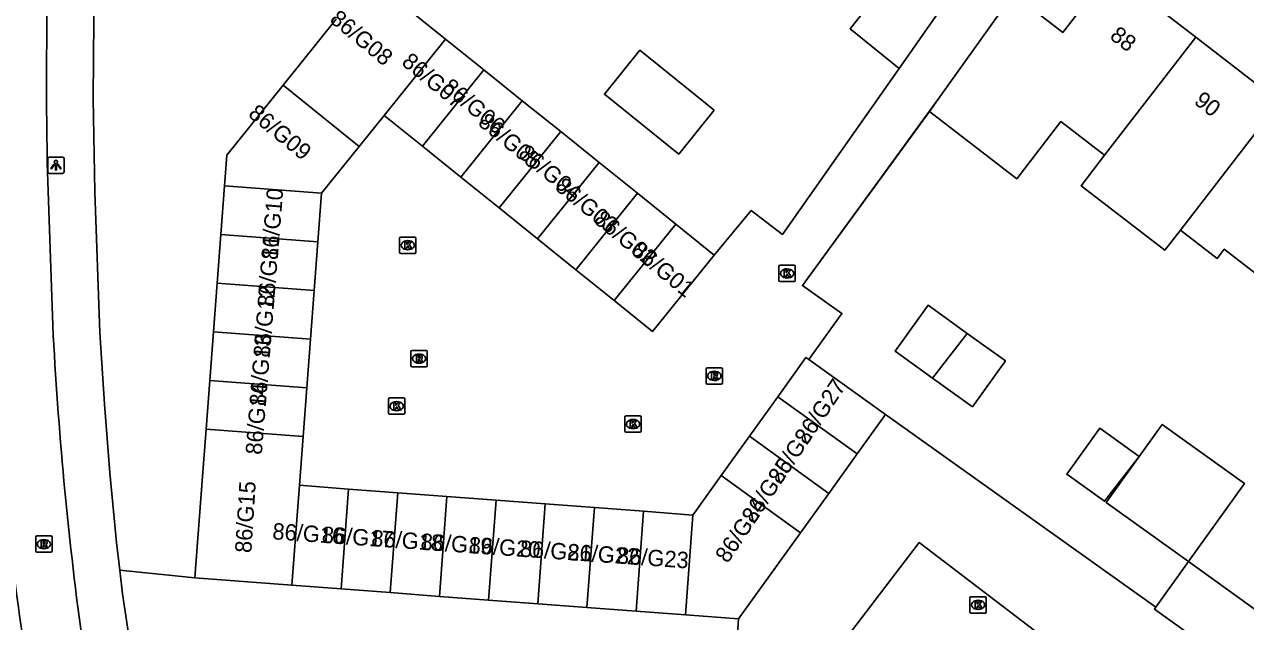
# Model space of a CAD drawing. Extents: x 160158 to 160921, y 381517 to 382041.
# Drawn here: x 160533.3 to 160607.8, y 381626.4 to 381662.9 of the extents above; entities that cross this region are included whole.
import ezdxf

# ---------------------------------------------------------------- set-up
doc = ezdxf.new("R2010")
doc.units = 0
for name, color, linetype in [('IMGEO_Fietspad_gesloten', 7, 'Continuous'), ('IMGEO_Groenvoorziening', 7, 'Continuous'), ('IMGEO_Kolk', 7, 'Continuous'), ('IMGEO_Lichtpunt', 7, 'Continuous'), ('IMGEO_Muur', 7, 'Continuous'), ('IMGEO_Pand', 7, 'Continuous'), ('IMGEO_Pand_nummerreeks', 7, 'Continuous'), ('IMGEO_Parkeervlak_open', 7, 'Continuous'), ('IMGEO_Rijbaan_lokaal_open', 7, 'Continuous'), ('IMGEO_Rioolput', 7, 'Continuous'), ('IMGEO_Voetpad_open', 7, 'Continuous')]:
    doc.layers.add(name, color=color, linetype=linetype)

msp = doc.modelspace()

# ---------------------------------------------------------------- linework, layer by layer
at = {"layer": 'IMGEO_Fietspad_gesloten'}
msp.add_lwpolyline([(160535.005, 381644.503), (160534.672, 381654.468)], dxfattribs=at)
for centre, radius, start, end in [((160815.535, 381659.561), 280.909, 175.73703, 181.03881), ((160691.29, 381649.45), 159.925, 181.41276, 189.10853), ((160764.179, 381656.242), 229.475, 182.93225, 187.69127)]:
    msp.add_arc(centre, radius, start, end, dxfattribs=at)
at = {"layer": 'IMGEO_Groenvoorziening'}
msp.add_lwpolyline([(160543.681, 381629.096), (160539.1, 381629.573)], dxfattribs=at)
at = {"layer": 'IMGEO_Kolk'}
for p, q in [((160556.181, 381648.991), (160556.181, 381649.843)), ((160556.256, 381649.917), (160557.108, 381649.917)), ((160556.669, 381649.697), (160556.694, 381649.697)), ((160557.182, 381649.843), (160557.182, 381648.991)), ((160557.108, 381648.917), (160556.256, 381648.917)), ((160556.692, 381649.137), (160556.667, 381649.137)), ((160579.348, 381647.268), (160579.348, 381648.12)), ((160579.423, 381648.194), (160580.275, 381648.194)), ((160580.349, 381648.12), (160580.349, 381647.268)), ((160579.859, 381647.414), (160579.834, 381647.414)), ((160579.836, 381647.974), (160579.861, 381647.974)), ((160580.275, 381647.194), (160579.423, 381647.194)), ((160555.506, 381639.162), (160555.506, 381640.014)), ((160555.581, 381640.088), (160556.433, 381640.088)), ((160555.994, 381639.868), (160556.019, 381639.868)), ((160556.507, 381640.014), (160556.507, 381639.162)), ((160556.017, 381639.308), (160555.992, 381639.308)), ((160556.433, 381639.088), (160555.581, 381639.088)), ((160569.938, 381638.065), (160569.938, 381638.917)), ((160570.013, 381638.991), (160570.865, 381638.991)), ((160570.426, 381638.771), (160570.451, 381638.771)), ((160570.939, 381638.917), (160570.939, 381638.065)), ((160570.865, 381637.991), (160570.013, 381637.991)), ((160570.449, 381638.211), (160570.424, 381638.211)), ((160591.084, 381627.948), (160591.936, 381627.948)), ((160591.009, 381627.022), (160591.009, 381627.874)), ((160591.497, 381627.728), (160591.522, 381627.728)), ((160592.01, 381627.874), (160592.01, 381627.022)), ((160591.936, 381626.948), (160591.084, 381626.948)), ((160591.52, 381627.168), (160591.495, 381627.168))]:
    msp.add_line(p, q, dxfattribs=at)
for points in [[(160556.181, 381648.991), (160556.181, 381649.843)], [(160556.256, 381649.917), (160557.108, 381649.917)], [(160556.502, 381649.617), (160556.625, 381649.617), (160556.625, 381649.466), (160556.755, 381649.617), (160556.919, 381649.617), (160556.773, 381649.466), (160556.926, 381649.217), (160556.774, 381649.217), (160556.689, 381649.381), (160556.625, 381649.314), (160556.625, 381649.217), (160556.502, 381649.217), (160556.502, 381649.617)], [(160557.182, 381649.843), (160557.182, 381648.991)], [(160557.108, 381648.917), (160556.256, 381648.917)], [(160579.348, 381647.268), (160579.348, 381648.12)], [(160579.423, 381648.194), (160580.275, 381648.194)], [(160580.349, 381648.12), (160580.349, 381647.268)], [(160579.669, 381647.894), (160579.792, 381647.894), (160579.792, 381647.743), (160579.922, 381647.894), (160580.086, 381647.894), (160579.94, 381647.743), (160580.093, 381647.494), (160579.941, 381647.494), (160579.856, 381647.658), (160579.792, 381647.591), (160579.792, 381647.494), (160579.669, 381647.494), (160579.669, 381647.894)], [(160580.275, 381647.194), (160579.423, 381647.194)], [(160555.506, 381639.162), (160555.506, 381640.014)], [(160555.581, 381640.088), (160556.433, 381640.088)], [(160556.507, 381640.014), (160556.507, 381639.162)], [(160555.827, 381639.788), (160555.95, 381639.788), (160555.95, 381639.637), (160556.08, 381639.788), (160556.244, 381639.788), (160556.098, 381639.637), (160556.251, 381639.388), (160556.099, 381639.388), (160556.014, 381639.552), (160555.95, 381639.485), (160555.95, 381639.388), (160555.827, 381639.388), (160555.827, 381639.788)], [(160556.433, 381639.088), (160555.581, 381639.088)], [(160569.938, 381638.065), (160569.938, 381638.917)], [(160570.013, 381638.991), (160570.865, 381638.991)], [(160570.259, 381638.691), (160570.382, 381638.691), (160570.382, 381638.54), (160570.512, 381638.691), (160570.676, 381638.691), (160570.53, 381638.54), (160570.683, 381638.291), (160570.531, 381638.291), (160570.446, 381638.455), (160570.382, 381638.388), (160570.382, 381638.291), (160570.259, 381638.291), (160570.259, 381638.691)], [(160570.939, 381638.917), (160570.939, 381638.065)], [(160570.865, 381637.991), (160570.013, 381637.991)], [(160591.084, 381627.948), (160591.936, 381627.948)], [(160591.009, 381627.022), (160591.009, 381627.874)], [(160591.33, 381627.648), (160591.453, 381627.648), (160591.453, 381627.497), (160591.583, 381627.648), (160591.747, 381627.648), (160591.601, 381627.497), (160591.754, 381627.248), (160591.602, 381627.248), (160591.517, 381627.412), (160591.453, 381627.345), (160591.453, 381627.248), (160591.33, 381627.248), (160591.33, 381627.648)], [(160592.01, 381627.874), (160592.01, 381627.022)], [(160591.936, 381626.948), (160591.084, 381626.948)]]:
    msp.add_lwpolyline(points, dxfattribs=at)
for centre, start, end in [((160556.258, 381649.841), 91.55205, 178.44795), ((160556.258, 381649.841), 91.55205, 178.44795), ((160557.106, 381649.841), 1.55205, 88.44795), ((160557.106, 381649.841), 1.55205, 88.44795), ((160556.258, 381648.993), 181.55205, 268.44795), ((160556.258, 381648.993), 181.55205, 268.44795), ((160557.106, 381648.993), 271.55205, 358.44795), ((160557.106, 381648.993), 271.55205, 358.44795), ((160579.425, 381648.118), 91.55205, 178.44795), ((160579.425, 381648.118), 91.55205, 178.44795), ((160580.273, 381648.118), 1.55205, 88.44795), ((160580.273, 381648.118), 1.55205, 88.44795), ((160579.425, 381647.27), 181.55205, 268.44795), ((160579.425, 381647.27), 181.55205, 268.44795), ((160580.273, 381647.27), 271.55205, 358.44795), ((160580.273, 381647.27), 271.55205, 358.44795), ((160555.583, 381640.012), 91.55205, 178.44795), ((160555.583, 381640.012), 91.55205, 178.44795), ((160556.431, 381640.012), 1.55205, 88.44795), ((160556.431, 381640.012), 1.55205, 88.44795), ((160555.583, 381639.164), 181.55205, 268.44795), ((160555.583, 381639.164), 181.55205, 268.44795), ((160556.431, 381639.164), 271.55205, 358.44795), ((160556.431, 381639.164), 271.55205, 358.44795), ((160570.015, 381638.915), 91.55205, 178.44795), ((160570.015, 381638.915), 91.55205, 178.44795), ((160570.863, 381638.915), 1.55205, 88.44795), ((160570.863, 381638.915), 1.55205, 88.44795), ((160570.015, 381638.067), 181.55205, 268.44795), ((160570.015, 381638.067), 181.55205, 268.44795), ((160570.863, 381638.067), 271.55205, 358.44795), ((160570.863, 381638.067), 271.55205, 358.44795), ((160591.086, 381627.872), 91.55205, 178.44795), ((160591.086, 381627.872), 91.55205, 178.44795), ((160591.934, 381627.872), 1.55205, 88.44795), ((160591.934, 381627.872), 1.55205, 88.44795), ((160591.086, 381627.024), 181.55205, 268.44795), ((160591.086, 381627.024), 181.55205, 268.44795), ((160591.934, 381627.024), 271.55205, 358.44795), ((160591.934, 381627.024), 271.55205, 358.44795)]:
    msp.add_arc(centre, 0.0765, start, end, dxfattribs=at)
for centre, major_axis, ratio, start_param, end_param in [((160556.668, 381649.417), (-0.387, 0.002), 0.722429, 4.712389, 7.853982), ((160556.693, 381649.417), (-0.39, 0.002), 0.717154, 1.570796, 4.712389), ((160579.835, 381647.694), (-0.387, 0.002), 0.722429, 4.712389, 7.853982), ((160579.86, 381647.694), (-0.39, 0.002), 0.717154, 1.570796, 4.712389), ((160555.993, 381639.588), (-0.387, 0.002), 0.722429, 4.712389, 7.853982), ((160556.018, 381639.588), (-0.39, 0.002), 0.717154, 1.570796, 4.712389), ((160570.425, 381638.491), (-0.387, 0.002), 0.722429, 4.712389, 7.853982), ((160570.45, 381638.491), (-0.39, 0.002), 0.717154, 1.570796, 4.712389), ((160591.496, 381627.448), (-0.387, 0.002), 0.722429, 4.712389, 7.853982), ((160591.521, 381627.448), (-0.39, 0.002), 0.717154, 1.570796, 4.712389)]:
    msp.add_ellipse(centre, major_axis=major_axis, ratio=ratio, start_param=start_param, end_param=end_param, dxfattribs=at)
at = {"layer": 'IMGEO_Lichtpunt'}
for p, q in [((160535.602, 381654.803), (160534.794, 381654.803)), ((160535.602, 381654.803), (160534.794, 381654.803)), ((160534.7, 381654.708), (160534.7, 381653.901)), ((160534.7, 381654.708), (160534.7, 381653.901)), ((160535.696, 381653.901), (160535.696, 381654.708)), ((160535.696, 381653.901), (160535.696, 381654.708)), ((160534.794, 381653.807), (160535.602, 381653.807)), ((160534.794, 381653.807), (160535.602, 381653.807))]:
    msp.add_line(p, q, dxfattribs=at)
for points in [[(160535.074, 381654.372), (160535.113, 381654.344), (160534.925, 381654.082), (160534.887, 381654.109), (160535.074, 381654.372)], [(160535.176, 381654.324), (160535.223, 381654.324), (160535.223, 381654.002), (160535.176, 381654.002), (160535.176, 381654.324)], [(160535.286, 381654.344), (160535.324, 381654.371), (160535.511, 381654.109), (160535.472, 381654.081), (160535.286, 381654.344)]]:
    msp.add_lwpolyline(points, dxfattribs=at)
msp.add_circle((160535.199, 381654.506), 0.0994, dxfattribs=at)
for centre, start, end in [((160534.794, 381654.708), 90, 180), ((160534.794, 381654.708), 90, 180), ((160535.602, 381654.708), 0, 90), ((160535.602, 381654.708), 0, 90), ((160534.794, 381653.901), 180, 270), ((160534.794, 381653.901), 180, 270), ((160535.602, 381653.901), 270, 0), ((160535.602, 381653.901), 270, 360)]:
    msp.add_arc(centre, 0.0946, start, end, dxfattribs=at)
at = {"layer": 'IMGEO_Muur'}
for points in [[(160577.655, 381651.538), (160579.562, 381650.074), (160586.695, 381660.204)], [(160583.195, 381645.251), (160580.788, 381646.954), (160589.08, 381658.343)]]:
    msp.add_lwpolyline(points, dxfattribs=at)
at = {"layer": 'IMGEO_Pand'}
for points in [[(160586.695, 381660.204), (160583.705, 381662.628), (160585.732, 381665.217), (160582.916, 381667.516), (160582.556, 381667.072), (160580.438, 381668.789)], [(160604.808, 381662.117), (160599.574, 381666.16), (160596.685, 381662.418), (160593.646, 381664.765)], [(160554.346, 381665.747), (160558.995, 381662.007)], [(160590.45, 381665.598), (160586.695, 381660.204)], [(160593.646, 381664.765), (160592.891, 381663.696), (160589.08, 381658.343), (160588.551, 381657.587)], [(160552.321, 381663.23), (160549.075, 381659.196)], [(160555.243, 381657.343), (160558.995, 381662.007)], [(160558.995, 381662.007), (160561.337, 381660.123)], [(160599.239, 381654.908), (160604.808, 381662.117)], [(160604.808, 381662.117), (160609.913, 381658.174)], [(160575.39, 381657.675), (160573.227, 381654.987), (160568.693, 381658.636), (160570.856, 381661.324), (160575.39, 381657.675)], [(160557.585, 381655.459), (160561.337, 381660.123)], [(160561.337, 381660.123), (160563.679, 381658.239)], [(160549.075, 381659.196), (160545.634, 381654.919), (160545.492, 381653.043)], [(160549.075, 381659.196), (160553.725, 381655.455)], [(160563.679, 381658.239), (160559.927, 381653.575)], [(160563.679, 381658.239), (160566.021, 381656.355)], [(160609.913, 381658.174), (160603.864, 381650.343)], [(160553.725, 381655.455), (160555.243, 381657.343)], [(160555.243, 381657.343), (160557.585, 381655.459)], [(160588.551, 381657.587), (160593.872, 381653.476), (160596.57, 381656.969), (160599.239, 381654.908)], [(160562.269, 381651.691), (160566.021, 381656.355)], [(160566.021, 381656.355), (160568.363, 381654.471)], [(160553.725, 381655.455), (160551.419, 381652.588)], [(160559.927, 381653.575), (160557.585, 381655.459)], [(160603.864, 381650.343), (160602.907, 381649.105), (160597.802, 381653.048), (160599.239, 381654.908)], [(160568.363, 381654.471), (160564.61, 381649.807)], [(160568.363, 381654.471), (160570.704, 381652.587)], [(160559.927, 381653.575), (160562.269, 381651.691)], [(160545.492, 381653.043), (160545.267, 381650.063)], [(160551.419, 381652.588), (160545.492, 381653.043)], [(160551.194, 381649.615), (160551.419, 381652.588)], [(160570.704, 381652.587), (160566.952, 381647.923)], [(160570.704, 381652.587), (160573.046, 381650.703)], [(160564.61, 381649.807), (160562.269, 381651.691)], [(160569.294, 381646.039), (160573.046, 381650.703)], [(160573.046, 381650.703), (160575.388, 381648.819)], [(160603.864, 381650.343), (160606.112, 381648.608), (160606.546, 381649.17), (160609.408, 381646.959)], [(160545.267, 381650.063), (160545.042, 381647.09)], [(160545.267, 381650.063), (160551.194, 381649.615)], [(160551.194, 381649.615), (160550.969, 381646.642)], [(160564.61, 381649.807), (160566.952, 381647.923)], [(160569.294, 381646.039), (160571.636, 381644.155), (160575.388, 381648.819)], [(160566.952, 381647.923), (160569.294, 381646.039)], [(160545.042, 381647.09), (160544.817, 381644.117)], [(160550.969, 381646.642), (160545.042, 381647.09)], [(160550.744, 381643.669), (160550.969, 381646.642)], [(160588.728, 381641.301), (160586.439, 381642.946), (160588.453, 381645.748), (160590.838, 381644.033)], [(160544.817, 381644.117), (160544.592, 381641.144)], [(160544.817, 381644.117), (160550.744, 381643.669)], [(160550.744, 381643.669), (160550.52, 381640.696)], [(160590.838, 381644.033), (160593.179, 381642.351), (160591.165, 381639.549), (160588.728, 381641.301)], [(160590.838, 381644.033), (160588.728, 381641.301)], [(160581.184, 381642.435), (160581.002, 381642.565), (160579.273, 381640.157)], [(160585.86, 381639.075), (160581.184, 381642.435)], [(160544.592, 381641.144), (160544.367, 381638.171)], [(160550.52, 381640.696), (160544.592, 381641.144)], [(160550.295, 381637.723), (160550.52, 381640.696)], [(160579.273, 381640.157), (160577.544, 381637.75)], [(160579.273, 381640.157), (160584.131, 381636.668)], [(160584.131, 381636.668), (160585.86, 381639.075)], [(160601.344, 381636.506), (160602.756, 381638.47), (160607.785, 381634.854), (160604.359, 381630.089)], [(160544.367, 381638.171), (160544.15, 381635.294), (160543.681, 381629.096)], [(160544.367, 381638.171), (160550.295, 381637.723)], [(160550.295, 381637.723), (160550.07, 381634.75)], [(160575.814, 381635.342), (160577.544, 381637.75)], [(160577.544, 381637.75), (160582.402, 381634.26)], [(160601.344, 381636.506), (160599.235, 381633.772), (160596.927, 381635.431), (160598.941, 381638.233), (160601.344, 381636.506)], [(160582.402, 381634.26), (160584.131, 381636.668)], [(160604.359, 381630.089), (160599.33, 381633.704), (160601.344, 381636.506)], [(160549.602, 381628.648), (160550.07, 381634.75)], [(160550.07, 381634.75), (160553.072, 381634.523)], [(160574.085, 381632.934), (160575.814, 381635.342)], [(160580.672, 381631.853), (160575.814, 381635.342)], [(160553.072, 381634.523), (160552.61, 381628.421)], [(160553.072, 381634.523), (160556.074, 381634.296)], [(160556.074, 381634.296), (160555.612, 381628.193)], [(160559.076, 381634.069), (160556.074, 381634.296)], [(160559.076, 381634.069), (160558.614, 381627.966)], [(160562.078, 381633.842), (160559.076, 381634.069)], [(160582.402, 381634.26), (160580.672, 381631.853)], [(160561.616, 381627.739), (160562.078, 381633.842)], [(160562.078, 381633.842), (160565.079, 381633.615)], [(160565.079, 381633.615), (160564.618, 381627.512)], [(160565.079, 381633.615), (160568.081, 381633.388)], [(160568.081, 381633.388), (160567.62, 381627.285)], [(160571.083, 381633.161), (160568.081, 381633.388)], [(160571.083, 381633.161), (160570.622, 381627.058)], [(160574.085, 381632.934), (160571.083, 381633.161)], [(160573.637, 381626.83), (160574.085, 381632.934)], [(160576.888, 381626.584), (160580.672, 381631.853)], [(160602.357, 381627.305), (160604.359, 381630.089)], [(160604.359, 381630.089), (160609.609, 381626.314), (160607.615, 381623.541)], [(160549.602, 381628.648), (160543.681, 381629.096)], [(160552.61, 381628.421), (160549.602, 381628.648)], [(160555.612, 381628.193), (160552.61, 381628.421)], [(160555.612, 381628.193), (160558.614, 381627.966)], [(160558.614, 381627.966), (160561.616, 381627.739)], [(160564.618, 381627.512), (160561.616, 381627.739)], [(160567.62, 381627.285), (160564.618, 381627.512)], [(160567.62, 381627.285), (160570.622, 381627.058)], [(160607.615, 381623.541), (160607.526, 381623.417), (160602.276, 381627.192), (160602.357, 381627.305)], [(160570.622, 381627.058), (160573.637, 381626.83)], [(160576.888, 381626.584), (160573.637, 381626.83)]]:
    msp.add_lwpolyline(points, dxfattribs=at)
at = {"layer": 'IMGEO_Parkeervlak_open'}
for points in [[(160585.86, 381639.075), (160602.357, 381627.305)], [(160576.509, 381621.016), (160576.888, 381626.584)]]:
    msp.add_lwpolyline(points, dxfattribs=at)
at = {"layer": 'IMGEO_Rijbaan_lokaal_open'}
for points in [[(160575.388, 381648.819), (160577.655, 381651.538), (160579.562, 381650.074), (160586.695, 381660.204)], [(160588.551, 381657.587), (160580.788, 381646.954), (160583.195, 381645.251), (160581.184, 381642.435)], [(160611.822, 381600.089), (160612.269, 381600.706), (160612.703, 381601.092), (160613.524, 381601.59), (160614.738, 381602.216), (160583.784, 381625.843), (160587.913, 381631.252), (160611.789, 381613.027)]]:
    msp.add_lwpolyline(points, dxfattribs=at)
at = {"layer": 'IMGEO_Rioolput'}
for p, q in [((160556.874, 381642.064), (160556.874, 381642.916)), ((160556.949, 381642.99), (160557.801, 381642.99)), ((160557.875, 381642.916), (160557.875, 381642.064)), ((160557.385, 381642.21), (160557.36, 381642.21)), ((160557.362, 381642.77), (160557.387, 381642.77)), ((160557.801, 381641.99), (160556.949, 381641.99)), ((160574.903, 381641.007), (160574.903, 381641.859)), ((160574.978, 381641.933), (160575.83, 381641.933)), ((160575.391, 381641.713), (160575.416, 381641.713)), ((160575.904, 381641.859), (160575.904, 381641.007)), ((160575.83, 381640.933), (160574.978, 381640.933)), ((160575.414, 381641.153), (160575.389, 381641.153)), ((160534.038, 381631.657), (160534.89, 381631.657)), ((160533.963, 381630.731), (160533.963, 381631.583)), ((160534.451, 381631.437), (160534.476, 381631.437)), ((160534.964, 381631.583), (160534.964, 381630.731)), ((160534.89, 381630.657), (160534.038, 381630.657)), ((160534.474, 381630.877), (160534.449, 381630.877))]:
    msp.add_line(p, q, dxfattribs=at)
for points in [[(160556.874, 381642.064), (160556.874, 381642.916)], [(160556.949, 381642.99), (160557.801, 381642.99)], [(160557.875, 381642.916), (160557.875, 381642.064)], [(160557.463, 381642.688), (160557.211, 381642.69), (160557.211, 381642.29)], [(160557.211, 381642.29), (160557.335, 381642.29), (160557.335, 381642.452), (160557.346, 381642.452)], [(160557.389, 381642.609), (160557.335, 381642.609), (160557.335, 381642.528)], [(160557.335, 381642.528), (160557.387, 381642.528)], [(160557.393, 381642.423), (160557.464, 381642.29), (160557.604, 381642.29), (160557.539, 381642.416)], [(160557.801, 381641.99), (160556.949, 381641.99)], [(160574.903, 381641.007), (160574.903, 381641.859)], [(160574.978, 381641.933), (160575.83, 381641.933)], [(160575.492, 381641.631), (160575.24, 381641.633), (160575.24, 381641.233)], [(160575.24, 381641.233), (160575.364, 381641.233), (160575.364, 381641.395), (160575.375, 381641.395)], [(160575.418, 381641.552), (160575.364, 381641.552), (160575.364, 381641.471)], [(160575.364, 381641.471), (160575.416, 381641.471)], [(160575.422, 381641.366), (160575.493, 381641.233), (160575.633, 381641.233), (160575.568, 381641.359)], [(160575.904, 381641.859), (160575.904, 381641.007)], [(160575.83, 381640.933), (160574.978, 381640.933)], [(160534.038, 381631.657), (160534.89, 381631.657)], [(160533.963, 381630.731), (160533.963, 381631.583)], [(160534.552, 381631.355), (160534.3, 381631.357), (160534.3, 381630.957)], [(160534.3, 381630.957), (160534.424, 381630.957), (160534.424, 381631.119), (160534.435, 381631.119)], [(160534.478, 381631.276), (160534.424, 381631.276), (160534.424, 381631.195)], [(160534.424, 381631.195), (160534.476, 381631.195)], [(160534.482, 381631.09), (160534.553, 381630.957), (160534.693, 381630.957), (160534.628, 381631.083)], [(160534.964, 381631.583), (160534.964, 381630.731)], [(160534.89, 381630.657), (160534.038, 381630.657)]]:
    msp.add_lwpolyline(points, dxfattribs=at)
for centre, radius, start, end in [((160556.951, 381642.914), 0.0765, 91.55205, 178.44795), ((160556.951, 381642.914), 0.0765, 91.55205, 178.44795), ((160557.799, 381642.914), 0.0765, 1.55205, 88.44795), ((160557.799, 381642.914), 0.0765, 1.55205, 88.44795), ((160557.345, 381642.399), 0.0533, 26.02933, 88.69889), ((160557.371, 381642.717), 0.19, 274.7715, 282.96867), ((160557.395, 381642.513), 0.0964, 77.00612, 93.18647), ((160557.409, 381642.57), 0.0378, 276.66336, 79.67722), ((160557.462, 381642.578), 0.109, 350.36119, 89.41601), ((160557.46, 381642.578), 0.112, 277.58423, 350.98172), ((160557.444, 381642.363), 0.108, 29.51342, 73.79051), ((160556.951, 381642.066), 0.0765, 181.55205, 268.44795), ((160556.951, 381642.066), 0.0765, 181.55205, 268.44795), ((160557.799, 381642.066), 0.0765, 271.55205, 358.44795), ((160557.799, 381642.066), 0.0765, 271.55205, 358.44795), ((160574.98, 381641.857), 0.0765, 91.55205, 178.44795), ((160574.98, 381641.857), 0.0765, 91.55205, 178.44795), ((160575.374, 381641.342), 0.0533, 26.02933, 88.69889), ((160575.4, 381641.66), 0.19, 274.7715, 282.96867), ((160575.424, 381641.456), 0.0964, 77.00612, 93.18647), ((160575.438, 381641.513), 0.0378, 276.66336, 79.67722), ((160575.491, 381641.521), 0.109, 350.36119, 89.41601), ((160575.489, 381641.521), 0.112, 277.58423, 350.98172), ((160575.473, 381641.306), 0.108, 29.51342, 73.79051), ((160575.828, 381641.857), 0.0765, 1.55205, 88.44795), ((160575.828, 381641.857), 0.0765, 1.55205, 88.44795), ((160574.98, 381641.009), 0.0765, 181.55205, 268.44795), ((160574.98, 381641.009), 0.0765, 181.55205, 268.44795), ((160575.828, 381641.009), 0.0765, 271.55205, 358.44795), ((160575.828, 381641.009), 0.0765, 271.55205, 358.44795), ((160534.04, 381631.581), 0.0765, 91.55205, 178.44795), ((160534.04, 381631.581), 0.0765, 91.55205, 178.44795), ((160534.888, 381631.581), 0.0765, 1.55205, 88.44795), ((160534.888, 381631.581), 0.0765, 1.55205, 88.44795), ((160534.434, 381631.066), 0.0533, 26.02933, 88.69889), ((160534.46, 381631.384), 0.19, 274.7715, 282.96867), ((160534.484, 381631.18), 0.0964, 77.00612, 93.18647), ((160534.498, 381631.237), 0.0378, 276.66336, 79.67722), ((160534.551, 381631.245), 0.109, 350.36119, 89.41601), ((160534.549, 381631.245), 0.112, 277.58423, 350.98172), ((160534.533, 381631.03), 0.108, 29.51342, 73.79051), ((160534.04, 381630.733), 0.0765, 181.55205, 268.44795), ((160534.04, 381630.733), 0.0765, 181.55205, 268.44795), ((160534.888, 381630.733), 0.0765, 271.55205, 358.44795), ((160534.888, 381630.733), 0.0765, 271.55205, 358.44795)]:
    msp.add_arc(centre, radius, start, end, dxfattribs=at)
for centre, major_axis, ratio, start_param, end_param in [((160557.361, 381642.49), (-0.387, 0.002), 0.722429, 4.712389, 7.853982), ((160557.386, 381642.49), (-0.39, 0.002), 0.717154, 1.570796, 4.712389), ((160575.39, 381641.433), (-0.387, 0.002), 0.722429, 4.712389, 7.853982), ((160575.415, 381641.433), (-0.39, 0.002), 0.717154, 1.570796, 4.712389), ((160534.45, 381631.157), (-0.387, 0.002), 0.722429, 4.712389, 7.853982), ((160534.475, 381631.157), (-0.39, 0.002), 0.717154, 1.570796, 4.712389)]:
    msp.add_ellipse(centre, major_axis=major_axis, ratio=ratio, start_param=start_param, end_param=end_param, dxfattribs=at)
at = {"layer": 'IMGEO_Voetpad_open'}
for points in [[(160539.1, 381629.573), (160538.905, 381631.265), (160538.494, 381635.504), (160538.166, 381639.708), (160537.881, 381644.095), (160537.582, 381652.686), (160537.482, 381658.369), (160537.509, 381663.201), (160537.596, 381667.162), (160537.734, 381671.359), (160538.007, 381676.697), (160538.139, 381678.786)], [(160539.1, 381629.573), (160539.268, 381628.112), (160539.804, 381624.471), (160540.699, 381618.781), (160541.327, 381615.289), (160542.986, 381606.358), (160543.812, 381602.537), (160544.77, 381598.431), (160545.63, 381594.93), (160546.369, 381592.056), (160547.472, 381587.803), (160549.461, 381580.561), (160551.343, 381574.307), (160552.879, 381569.452), (160554.535, 381564.993)]]:
    msp.add_lwpolyline(points, dxfattribs=at)

# ---------------------------------------------------------------- texts
at = {"layer": 'IMGEO_Pand_nummerreeks'}
for s, rotation, p in [('86/G08', 320.57761, (160551.856, 381663.101)), ('88', 322.31657, (160599.491, 381662.08)), ('86/G07', 320.57761, (160556.246, 381660.487)), ('86/G06', 320.57761, (160558.719, 381658.922)), ('90', 322.31727, (160604.638, 381658.103)), ('86/G09', 320.57761, (160546.879, 381657.332)), ('86/G05', 320.57761, (160560.909, 381656.808)), ('86/G04', 320.57761, (160563.361, 381654.882)), ('86/G03', 320.57761, (160565.611, 381652.867)), ('86/G10', 85.37186, (160548.732, 381648.491)), ('86/G02', 320.57761, (160567.983, 381650.855)), ('86/G11', 85.37186, (160548.5, 381645.623)), ('86/G01', 320.57761, (160570.269, 381648.947)), ('86/G12', 85.37186, (160548.249, 381642.533)), ('86/G13', 85.37186, (160548.009, 381639.566)), ('86/G14', 85.37186, (160547.768, 381636.592)), ('86/G27', 56.21282, (160581.047, 381637.157)), ('86/G26', 56.21282, (160579.437, 381634.749)), ('86/G25', 56.21282, (160577.826, 381632.342)), ('86/G15', 86.36705, (160547.128, 381630.596)), ('86/G24', 56.21282, (160576.215, 381629.934)), ('86/G16', 355.97409, (160548.392, 381631.458)), ('86/G17', 355.97409, (160551.411, 381631.246)), ('86/G18', 355.97409, (160554.432, 381631.033)), ('86/G19', 355.97409, (160557.444, 381630.821)), ('86/G20', 355.97409, (160560.377, 381630.615)), ('86/G21', 355.97409, (160563.503, 381630.395)), ('86/G22', 355.97409, (160566.404, 381630.19)), ('86/G23', 355.97409, (160569.429, 381629.977))]:
    msp.add_text(s, height=1, rotation=rotation, dxfattribs=at).set_placement(p)

doc.saveas('drawing.dxf')
